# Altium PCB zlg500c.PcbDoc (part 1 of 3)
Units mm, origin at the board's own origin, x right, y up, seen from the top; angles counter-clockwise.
Board outline 135.13 x 130.56 mm, 2 copper layers (Top Layer, Bottom Layer); 79 components, 87 nets, 356 pads, 44 vias.
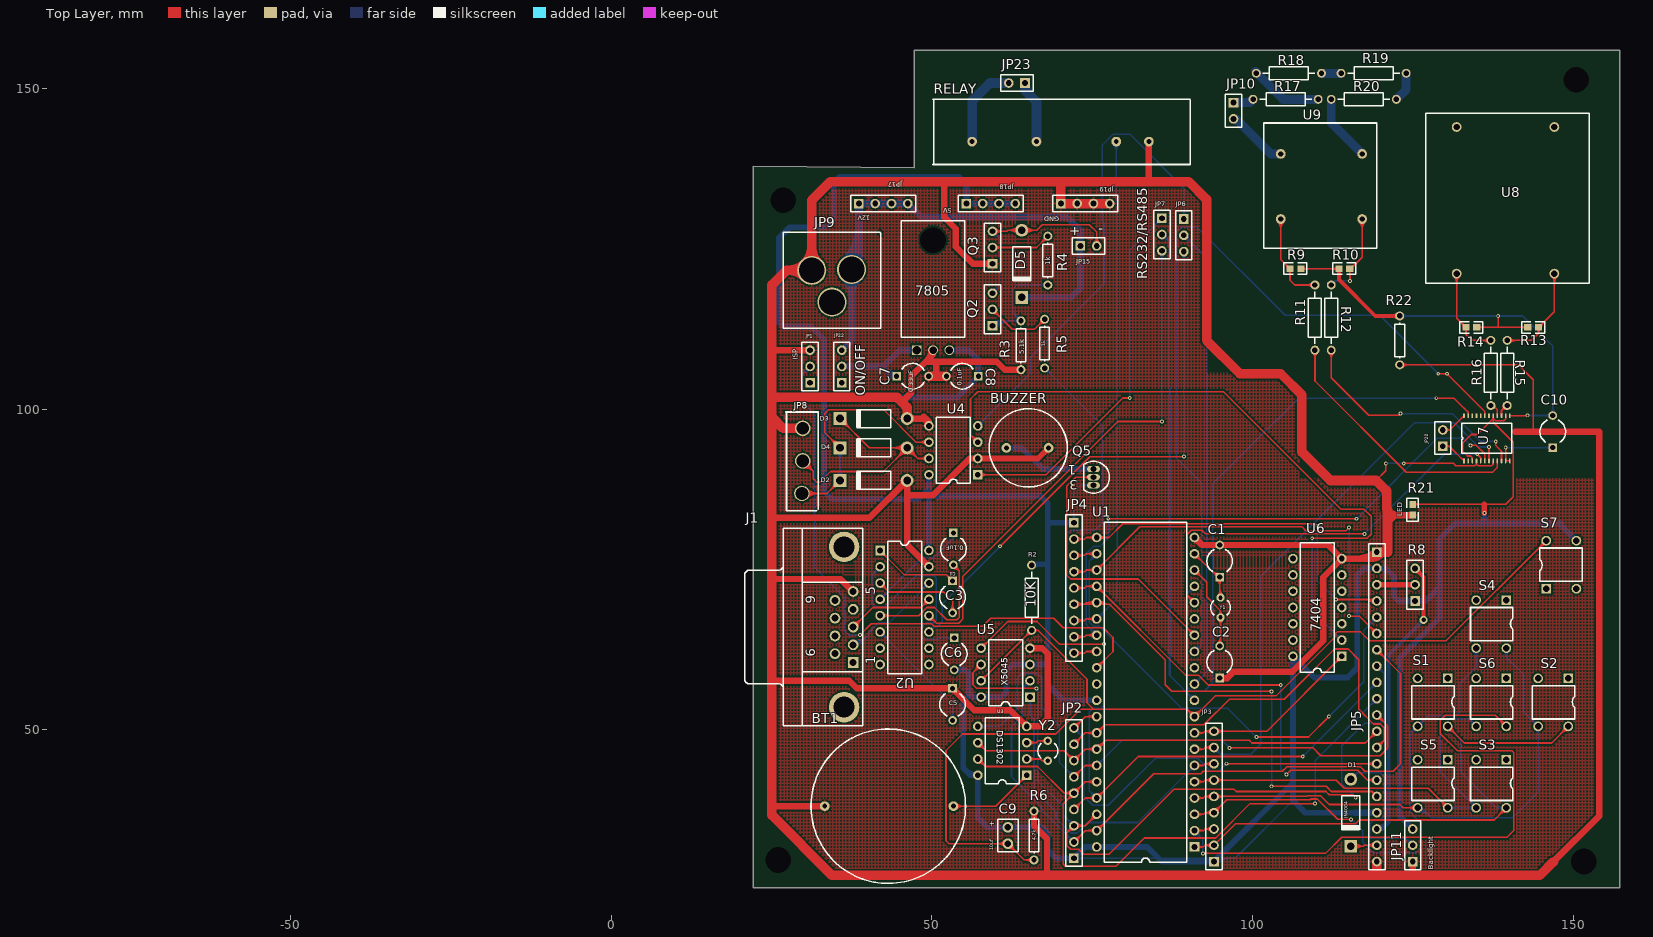
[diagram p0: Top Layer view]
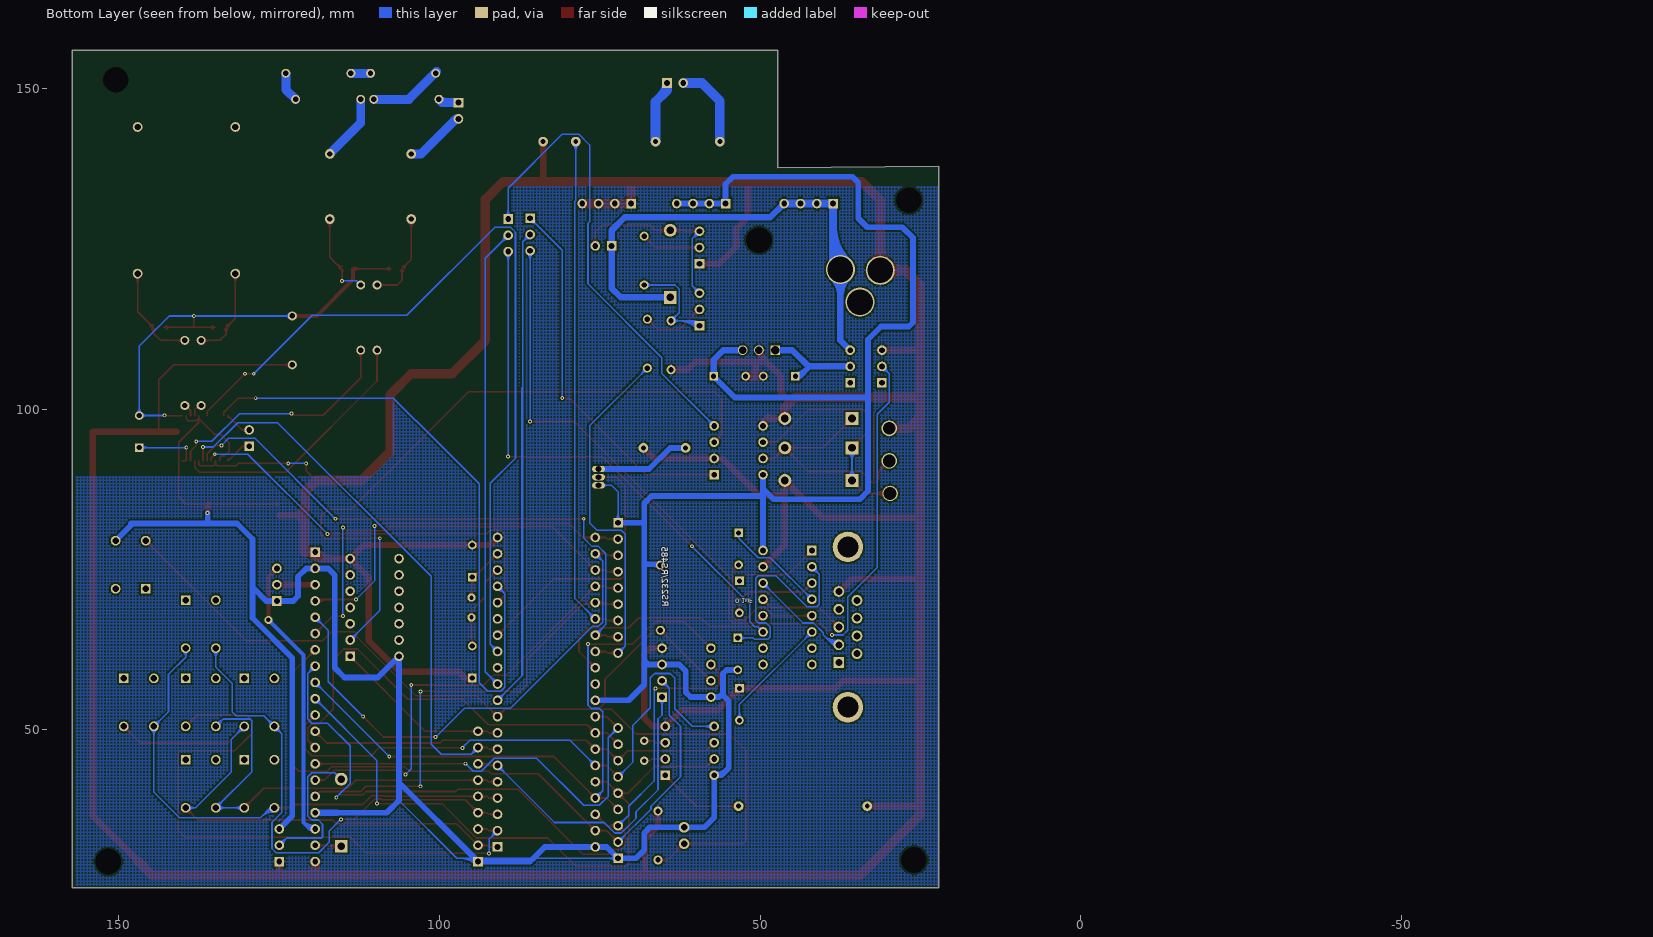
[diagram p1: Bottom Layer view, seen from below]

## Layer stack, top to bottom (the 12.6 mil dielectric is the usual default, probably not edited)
Top Layer: signal copper 0.0356
Dielectric: dielectric 0.32, FR-4, Dk 4.8
Bottom Layer: signal copper 0.0356

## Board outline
22.098,137.922 22.098,25.4 157.226,25.4 157.226,155.956 47.244,155.956 47.244,137.668

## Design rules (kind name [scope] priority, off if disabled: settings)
Clearance [All] p1: gap=0.254
ComponentClearance [All] p1: gap=0.254 collisioncheckmode=0
PolygonConnect [All] p1: connectstyle=Relief reliefconductorwidth=0.254 reliefentries=4 polygonreliefangle="90 Angle"
RoomDefinition zlg500c [InComponentClass('zlg500c')] p1: confinementstyle=ConfineIn formatcopy=TRUE outline 1.397,0 52.197,0 52.197,25.4 1.397,25.4
RoutingLayers [All] p1: top layer=Horizontal bottom layer=Vertical
RoutingVias [All] p1: holewidth=0.3 width=0.6 viastyle="Through Hole" minholewidth=0.3 minwidth=0.6 maxholewidth=0.3 maxwidth=0.6
SolderMaskExpansion [All] p1: expansion=0.102
TestPointUsage [All] p1: valid=0 allowmultiple=FALSE
Testpoint [All] p1: side=15 testpointundercomponent=TRUE minsize=1.016 maxsize=2.54 preferedsize=1.524 minholesize=0 maxholesize=1.016 preferedholesize=0.813 testpointgrid=0.025 style=1023 order=-539222988
Width Width_1 [(InNet('VEE'))] p1: maxlimit=0.6 minlimit=0.254 preferedwidth=0.254 toplayer_minwidth=0.54 toplayer_prefwidth=0.6 bottomlayer_prefwidth=0.6 minimp=50.000000 maximp=50.000000 favimp=50.000000
Width [All] p2: maxlimit=1.5 minlimit=0.2 preferedwidth=0.254 toplayer_prefwidth=1.5 bottomlayer_prefwidth=1 minimp=50.000000 maximp=50.000000 favimp=50.000000
16 further rules are at their usual default settings.

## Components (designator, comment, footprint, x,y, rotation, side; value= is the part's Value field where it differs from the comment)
7805 "7805" T0220 50.165,120.904 r0 top
BT1 "Battery" BATTERY 43.18,38.1 r270 top
BUZZER "BUZZER" BUZZER 62.484,116.84 r180 top
C1 "Cap2" CAPR5-4X5 94.869,76.327 r90 top
C2 "Cap2" CAPR5-4X5 94.869,60.579 r90 top
C3 "Cap2" CAPR5-4X5 53.213,70.739 r270 top
C4 "Cap2" CAPR5-4X5 53.34,78.232 r270 top
C5 "Cap2" CAPR5-4X5 53.213,53.975 r270 top
C6 "Cap2" CAPR5-4X5 53.467,61.849 r270 top
C7 "Cap2" CAPR5-4X5 46.989,105.156 r0 top
C8 "Cap2" CAPR5-4X5 54.737,105.156 r180 top
C9 "Cap" CAPR2.54-5.1X3.2 61.849,33.528 r90 top
C10 "Cap2" CAPR5-4X5 146.812,96.52 r90 top
D1 "Diode 1N4004" DIO10.46-5.3x2.8 115.316,37.084 r270 top
D2 "Diode 11DQ03" DIO10.46-5.3x2.8 40.894,88.9 r180 top
D3 "Diode 11DQ03" DIO10.46-5.3x2.8 40.894,98.552 r180 top
D4 "Diode 11DQ03" DIO10.46-5.3x2.8 40.894,93.98 r180 top
D5 "Diode 1N4004" DIO10.46-5.3x2.8 64.008,122.682 r270 top
J1 "D Connector 9" DSUB1.385-2H9 26.797,66.04 r90 top
JP1 "Header 3" HDR1X3 30.988,104.14 r90 top
JP2 "Header 9" HDR1X9 72.136,29.972 r90 top
JP3 "Header 9" HDR1X9 93.98,29.464 r90 top
JP4 "Header 9" HDR1X9 72.136,82.296 r270 top
JP5 "Header 20" HDR1X20 119.38,77.724 r270 top
JP6 "Header 3" HDR1X3 89.281,129.667 r270 top
JP7 "Header 3" HDR1X3 85.852,129.794 r270 top
JP8 "Header 3" RS485 29.718,91.948 r90 top
JP9 "POWERSLOT" POWERSLOT 34.036,120.396 r180 top
JP10 "Header 2" HDR1X2 97.028,147.828 r270 top
JP11 "Header 3" HDR1X3 124.968,29.464 r90 top
JP15 "Header 2" HDR1X2 73.152,125.476 r0 top
JP17 "Header 4" HDR1X4 38.608,132.08 r0 top
JP18 "Header 4" HDR1X4 55.372,132.08 r0 top
JP19 "Header 4" HDR1X4 70.104,132.08 r0 top
JP20 "Header 2" HDR1X2 129.667,94.234 r90 top
JP22 "Header 3" HDR1X3 35.941,104.14 r90 top
JP23 "AC connector" HDR1X2 64.516,150.876 r180 top
Q2 "2N3904" HDR1X3 59.436,113.03 r90 top
Q3 "2N3904" HDR1X3 59.436,122.682 r90 top
Q5 "2N3904" BCY-W3/E4 75.184,89.408 r180 top
R2 "Res2" AXIAL-0.4 65.532,70.612 r90 top
R3 "Res1" AXIAL-0.3 63.881,109.982 r90 top
R4 "Res1" AXIAL-0.3 68.072,123.19 r270 top
R5 "Res1" AXIAL-0.3 67.564,110.236 r270 top
R6 "Res1" AXIAL-0.3 65.913,33.528 r270 top
R8 "R" HDR1X3 125.349,70.104 r90 top
R9 "Res3" C1608-0603 106.68,121.92 r0 top
R10 "Res3" C1608-0603 114.3,121.92 r0 top
R11 "Res2" AXIAL-0.4 109.728,114.3 r270 top
R12 "Res2" AXIAL-0.4 112.268,114.3 r270 top
R13 "Res3" C1608-0603 143.764,112.776 r180 top
R14 "Res3" C1608-0603 134.112,112.776 r180 top
R15 "Res2" AXIAL-0.4 139.7,105.664 r270 top
R16 "Res2" AXIAL-0.4 137.16,105.664 r270 top
R17 "Res2" AXIAL-0.4 105.156,148.336 r180 top
R18 "Res2" AXIAL-0.4 105.664,152.4 r180 top
R19 "Res2" AXIAL-0.4 118.872,152.4 r180 top
R20 "Res2" AXIAL-0.4 117.348,148.336 r180 top
R21 "Res3" C1608-0603 124.968,84.328 r90 top
R22 "Res1" AXIAL-0.3 122.936,110.744 r270 top
RELAY "Relay_400V5A" RELAY_400V5A 116.332,115.316 r0 top
S1 "" SW_4 128.524,53.848 r270 top
S2 "" SW_4 147.32,53.848 r270 top
S3 "" SW_4 137.668,41.148 r270 top
S4 "" SW_4 137.668,66.04 r270 top
S5 "" SW_4 128.524,41.148 r270 top
S6 "" SW_4 137.668,53.848 r270 top
S7 "" SW_4 147.701,76.2 r90 top
U1 "P89C51RD2HBP" SOT129-1 83.312,55.88 r90 top
U2 "MAX232ACPE" DIP-16 45.72,69.088 r270 top
U3 "DS1302" DIP-8 60.96,46.736 r90 top
U4 "MAX485CPA" DIP-8 53.34,93.599 r90 top
U5 "X5045" dip-8 61.468,58.928 r90 top
U6 "7404" DIP-14 110.109,69.088 r90 top
U7 "CS5460A-BSZ" SOP24 132.969,91.948 r90 top
U8 "TA1419" TA1419 141.732,136.144 r0 top
U9 "TV1013" TV1013 99.06,121.92 r270 top
Y1 "XTAL" BCY-W2/D3.1 94.996,69.088 r0 top
Y2 "XTAL" BCY-W2/D3.1 68.072,46.736 r0 top

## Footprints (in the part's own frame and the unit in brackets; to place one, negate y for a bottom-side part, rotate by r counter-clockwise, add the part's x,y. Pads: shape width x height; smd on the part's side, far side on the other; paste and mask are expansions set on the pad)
AXIAL-0.3 [mm]
  round 1.4 hole 0.85: 1(-3.81,0) 2(3.81,0)
  silkscreen extent -2.77,-0.76 2.77,0.76
AXIAL-0.4 [mm]
  round 1.4 hole 0.85: 1(-5.08,0) 2(5.08,0)
  silkscreen extent -4.06,-1.02 4.06,1.02
BATTERY [mil]
  round 60 hole 30: 1(0,400) 2(0,-390)
  silkscreen extent -474,-474 474,474
BCY-W2/D3.1 [mm]
  round 1.3 hole 0.7: 1(0,1.55) 2(0,-1.55)
  silkscreen extent -1.55,-1.19 1.55,1.17
BCY-W3/E4 [mm]
  oval 2x1 hole 0.9: 1(0,-1.27) 2(0,0) 3(0,1.27)
  silkscreen extent -2.48,-2.48 1.5,2.48
BUZZER [mil]
  round 60 hole 31.5: 0(-225,900) 1(35,900)
  silkscreen extent -340,660 140,1140
C1608-0603 [mm]
  rect 1.1x1 smd: 1(-0.85,0) 2(0.85,0)
  silkscreen extent -1.8,-0.9 1.8,0.9
CAPR2.54-5.1X3.2 [mm]
  round 1.65 hole 1: 1(-1.27,0) 2(1.27,0)
  silkscreen extent -2.55,-1.6 2.55,1.6
CAPR5-4X5 [mm]
  rect 1.35x1.35 hole 0.8: 1(-2.5,0)
  round 1.35 hole 0.8: 2(2.5,0)
  silkscreen extent -1.69,-2 1.82,2
DIO10.46-5.3x2.8 [mm]
  round 2 hole 1.2: 1(-5.23,0)
  rect 2x2 hole 1.2: 2(5.23,0)
  silkscreen extent -2.65,-1.41 2.74,1.4
DIP-8 [mm]
  rect 1.5x1.5 hole 0.9: 1(-3.81,-3.81)
  round 1.5 hole 0.9: 2(-1.27,-3.81) 3(1.27,-3.81) 4(3.81,-3.81) 5(3.81,3.81) 6(1.27,3.81) 7(-1.27,3.81) 8(-3.81,3.81)
  silkscreen extent -5.15,-2.65 5.15,2.65
dip-8 [mm]
  rect 1.5x1.5 hole 0.9: 1(-3.81,-3.81)
  round 1.5 hole 0.9: 2(-1.27,-3.81) 3(1.27,-3.81) 4(3.81,-3.81) 5(3.81,3.81) 6(1.27,3.81) 7(-1.27,3.81) 8(-3.81,3.81)
  silkscreen extent -5.15,-2.65 5.15,2.65
DIP-14 [mm]
  rect 1.5x1.5 hole 0.9: 1(-7.62,-3.81)
  round 1.5 hole 0.9: 2(-5.08,-3.81) 3(-2.54,-3.81) 4(0,-3.81) 5(2.54,-3.81) 6(5.08,-3.81) 7(7.62,-3.81) 8(7.62,3.81) 9(5.08,3.81) 10(2.54,3.81) 11(0,3.81) 12(-2.54,3.81) 13(-5.08,3.81) 14(-7.62,3.81)
  silkscreen extent -10.1,-2.65 10.1,2.65
DIP-16 [mm]
  rect 1.5x1.5 hole 0.9: 1(-8.89,-3.81)
  round 1.5 hole 0.9: 2(-6.35,-3.81) 3(-3.81,-3.81) 4(-1.27,-3.81) 5(1.27,-3.81) 6(3.81,-3.81) 7(6.35,-3.81) 8(8.89,-3.81) 9(8.89,3.81) 10(6.35,3.81) 11(3.81,3.81) 12(1.27,3.81) 13(-1.27,3.81) 14(-3.81,3.81) 15(-6.35,3.81) 16(-8.89,3.81)
  silkscreen extent -10.3,-2.65 10.3,2.65
DSUB1.385-2H9 [mm] "Connector; D Subminiature; 9 Position; Right Angle; Pitch 1.385 mm"
  rect 1.69x1.69 hole 1.09: 1(-5.54,-10.92)
  round 1.69 hole 1.09: 2(-2.77,-10.92) 3(0,-10.92) 4(2.77,-10.92) 5(5.54,-10.92) 6(-4.155,-8.08) 7(-1.385,-8.08) 8(1.385,-8.08) 9(4.155,-8.08)
  round 4.76 hole 3.26: 10(-12.495,-9.5) 11(12.495,-9.5)
  silkscreen extent -15.4,-12.4 15.4,6
HDR1X2 [mm] "Connector; Header; 2 Position"
  rect 1.5x1.5 hole 0.9: 1(0,0)
  round 1.5 hole 0.9: 2(2.54,0)
  silkscreen extent -1.27,-1.27 3.81,1.27
HDR1X3 [mm] "Connector; Header; 3 Position"
  rect 1.5x1.5 hole 0.9: 1(0,0)
  round 1.5 hole 0.9: 2(2.54,0) 3(5.08,0)
  silkscreen extent -1.27,-1.27 6.35,1.27
HDR1X4 [mm] "Connector; Header; 4 Position"
  rect 1.5x1.5 hole 0.9: 1(0,0)
  round 1.5 hole 0.9: 2(2.54,0) 3(5.08,0) 4(7.62,0)
  silkscreen extent -1.27,-1.27 8.89,1.27
HDR1X9 [mm] "Connector; Header; 9 Position"
  rect 1.5x1.5 hole 0.9: 1(0,0)
  round 1.5 hole 0.9: 2(2.54,0) 3(5.08,0) 4(7.62,0) 5(10.16,0) 6(12.7,0) 7(15.24,0) 8(17.78,0) 9(20.32,0)
  silkscreen extent -1.27,-1.27 21.59,1.27
HDR1X20 [mm] "Connector; Header; 20 Position"
  rect 1.5x1.5 hole 0.9: 1(0,0)
  round 1.5 hole 0.9: 2(2.54,0) 3(5.08,0) 4(7.62,0) 5(10.16,0) 6(12.7,0) 7(15.24,0) 8(17.78,0) 9(20.32,0) 10(22.86,0) 11(25.4,0) 12(27.94,0) 13(30.48,0) 14(33.02,0) 15(35.56,0) 16(38.1,0) 17(40.64,0) 18(43.18,0) 19(45.72,0) 20(48.26,0)
  silkscreen extent -1.27,-1.27 49.53,1.27
POWERSLOT [mil]
  round 178.11 hole 157.48: 1(-15,145) 2(110,-50) 3(-135,-55)
  Top Layer lines w10: -310,-285 -310,-275 -315,-270
  silkscreen extent -315,-285 285,305
RELAY_400V5A [mil]
  round 60 hole 30: 0(-1280,1040) 1(-1480,1040) 2(-1970,1040) 3(-2365,1040)
  silkscreen extent -2605,900 -1025,1300
RS485 [mm]
  round 2.424 hole 2: 1(-5.08,0) 2(0,-0.127) 3(5.08,-0.127)
  Top Layer lines w0.254: 7.62,2.54 7.493,2.413 ; -7.747,-2.286 -7.493,-2.54 ; -2.794,-2.54 7.62,-2.54
  silkscreen extent -7.75,-2.54 7.62,2.54
SOP24 [mm]
  rect 0.75x0.26 smd: 1(0,0)
  oval 0.75x0.26 smd: 2(0,-0.65) 3(0,-1.3) 4(0,-1.95) 5(0,-2.6) 6(0,-3.25) 7(0,-3.9) 8(0,-4.55) 9(0,-5.2) 10(0,-5.85) 11(0,-6.5) 12(0,-7.15) 13(7.05,-7.15) 14(7.05,-6.5) 15(7.05,-5.85) 16(7.05,-5.2) 17(7.05,-4.55) 18(7.05,-3.9) 19(7.05,-3.25) 20(7.05,-2.6) 21(7.05,-1.95) 22(7.05,-1.3) 23(7.05,-0.65) 24(7.05,0)
  silkscreen extent 1.21,-7.48 5.84,0.33
SOT129-1 [mm] "DIP; 40 Leads; Row Spacing 15.24 mm; Pitch 2.54 mm"
  rect 1.5x1.5 hole 0.9: 1(-24.13,-7.62)
  round 1.5 hole 0.9: 2(-21.59,-7.62) 3(-19.05,-7.62) 4(-16.51,-7.62) 5(-13.97,-7.62) 6(-11.43,-7.62) 7(-8.89,-7.62) 8(-6.35,-7.62) 9(-3.81,-7.62) 10(-1.27,-7.62) 11(1.27,-7.62) 12(3.81,-7.62) 13(6.35,-7.62) 14(8.89,-7.62) 15(11.43,-7.62) 16(13.97,-7.62) 17(16.51,-7.62) 18(19.05,-7.62) 19(21.59,-7.62) 20(24.13,-7.62) 21(24.13,7.62) 22(21.59,7.62) 23(19.05,7.62) 24(16.51,7.62) 25(13.97,7.62) 26(11.43,7.62) 27(8.89,7.62) 28(6.35,7.62) 29(3.81,7.62) 30(1.27,7.62) 31(-1.27,7.62) 32(-3.81,7.62) 33(-6.35,7.62) 34(-8.89,7.62) 35(-11.43,7.62) 36(-13.97,7.62) 37(-16.51,7.62) 38(-19.05,7.62) 39(-21.59,7.62) 40(-24.13,7.62)
  silkscreen extent -26.5,-6.45 26.5,6.45
SW_4 [mil]
  rect 60x60 hole 39.37: 1(-165,75)
  round 60 hole 39.37: 2(-165,-110) 3(130,-110) 4(130,75)
  silkscreen extent -120,-145 85,115
T0220 [mil] "T0220"
  rect 60x60 hole 53.62: 0(-100,-460)
  round 60 hole 45.75: 1(0,-460) 2(100,-460)
  round 0 hole 157.48: 4(0,215)
  silkscreen extent -195,-380 195,335
TA1419 [mil]
  round 60 hole 39.37: 1(-390,-590) 2(210,-590) 3(210,310) 4(-390,310)
  silkscreen extent -580,-650 425,395
TV1013 [mil]
  round 60 hole 31.5: 1(-705,710) 2(-705,210) 3(-305,210) 4(-305,710)
  silkscreen extent -895,105 -125,800

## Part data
BT1: "Multicell Battery"
C1 C2 C3 C4 C5 C6 C9 C10: "Capacitor"
C7 C8: library part Cap, "Capacitor"
D1 D5: "1 Amp General Purpose Rectifier"
D2 D3 D4: library part "Diode 18TQ045", "Schottky Rectifier"
J1: "Receptacle Assembly, 9 Position, Right Angle"
JP1 JP6 JP7 JP8 JP11 JP22: "Header, 3-Pin"
JP2 JP3 JP4: "Header, 9-Pin"
JP5: "Header, 20-Pin"
JP9: library part "Header 3", "Header, 3-Pin"
JP10 JP15 JP20: "Header, 2-Pin"
JP17 JP18 JP19: "Header, 4-Pin"
JP23: library part "Header 2", "Header, 2-Pin"
Q2 Q3 Q5: "NPN General Purpose Amplifier"
R2 R3 R4 R5 R6 R11 R12 R15 R16 R17 R18 R19 R20 R21 R22: "Resistor"
R8: library part RPot, "Potentiometer"
R9 R10 R13 R14: library part Res2, "Resistor"
S1 S2 S3 S4 S5 S6: library part SW-PB, "Switch"
S7: library part SW-DPST, "Double-Pole, Single-Throw Switch"
U1: "80C51 8-Bit Flash Microcontroller Family, 64 kB ISP/IAP Flash with 1 kB RAM."
U2: "+5V Powered, Multi-Channel RS-232 Driver/Receiver"
U3: "Trickle Charge Timekeeping Chip"
U4: "Low-Power, Slew-Rate-Limited RS-485/RS-422 Transceiver"
U6: library part 74AC04PC, "Hex Inverter"
Y1 Y2: "Crystal Oscillator"

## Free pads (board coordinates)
  round 0 hole 4: 0(-82.042,29.972) 0(-81.661,120.523) 0(-79.756,118.618) 0(26.035,29.718) 0(26.797,132.588) 0(150.495,151.384) 0(151.638,29.464)

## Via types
v1: diameter 0.6, hole 0.3, Top Layer to Bottom Layer, 43 vias
v2: diameter 1.27, hole 0.711, Top Layer to Bottom Layer, 1 vias

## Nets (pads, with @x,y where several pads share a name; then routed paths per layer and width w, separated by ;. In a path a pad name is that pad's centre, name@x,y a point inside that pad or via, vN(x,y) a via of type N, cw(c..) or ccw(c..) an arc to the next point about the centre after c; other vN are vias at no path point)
A: D1.2 JP5.19 | length 12.9
  Top Layer w0.254: D1.2@115.316,31.854 117.272,31.854 ; D1.2@115.777,31.441 cw(c116.703,30.61) 116.703,31.854 cw(c116.703,33.098) D1.2@115.777,32.267 ; D1.2@115.966,31.271 cw(c117.272,30.1) 117.272,31.854 ; D1.2@115.966,32.437 ccw(c117.272,33.608) 117.272,31.854 ; JP5.19@118.939,31.563 ccw(c117.876,30.5) 117.876,32.004 ccw(c117.876,33.508) JP5.19@118.939,32.445 ; JP5.19@119.119,31.743 ccw(c118.489,31.113) 118.489,32.004 ccw(c118.489,32.895) JP5.19@119.119,32.265 ; JP5.19@119.38,32.004 117.422,32.004 117.272,31.854
AD0: JP2.2 JP5.7 U1.39 U5.2 | length 143.8
  Top Layer w0.254: JP2.2@72.136,32.512 73.914,34.29 U1.39@75.692,34.29 84.582,43.18 91.948,43.18 92.304,43.536 104.623,43.536 105.308,44.221 116.847,44.221 117.507,43.561 121.92,43.561 123.063,44.704 123.063,58.801 JP5.7@119.38,62.484 ; JP5.7@119.38,61.861 cw(c119.38,60.357) 120.444,61.42 cw(c121.507,62.484) JP5.7@120.003,62.484 ; JP5.7@119.38,62.115 cw(c119.38,61.224) 120.01,61.854 cw(c120.64,62.484) JP5.7@119.749,62.484 ; 72.766,33.142 cw(c72.136,33.772) 72.136,32.881 ccw(c72.136,33.772) 72.766,33.142 ; 72.766,33.142 ccw(c73.396,32.512) 72.505,32.512 cw(c73.396,32.512) 72.766,33.142 ; 73.2,33.576 cw(c72.136,34.639) 72.136,33.135 ccw(c72.136,34.639) 73.2,33.576 ; 73.2,33.576 ccw(c74.263,32.512) 72.759,32.512 cw(c74.263,32.512) 73.2,33.576 ; 74.188,34.29 cw(c74.188,32.786) 75.251,33.849 ccw(c74.188,32.786) 74.188,34.29 ; 74.188,34.29 ccw(c74.188,35.794) 75.251,34.731 cw(c74.188,35.794) 74.188,34.29 ; 74.801,34.29 cw(c74.801,33.399) 75.431,34.029 ccw(c74.801,33.399) 74.801,34.29 ; 74.801,34.29 ccw(c74.801,35.181) 75.431,34.551 cw(c74.801,35.181) 74.801,34.29 ; 76.322,34.92 cw(c75.692,35.55) 75.692,34.659 ccw(c75.692,35.55) 76.322,34.92 ; 76.322,34.92 ccw(c76.952,34.29) 76.061,34.29 cw(c76.952,34.29) 76.322,34.92 ; 76.756,35.354 cw(c75.692,36.417) 75.692,34.913 ccw(c75.692,36.417) 76.756,35.354 ; 76.756,35.354 ccw(c77.819,34.29) 76.315,34.29 cw(c77.819,34.29) 76.756,35.354
  Bottom Layer w0.254: U5.2@65.278,57.658 64.135,56.515 64.135,52.273 62.408,50.546 62.408,42.697 67.005,38.1 67.005,37.643 JP2.2@72.136,32.512 ; JP2.2@71.513,32.512 ccw(c70.009,32.512) 71.072,33.576 ccw(c72.136,34.639) JP2.2@72.136,33.135 ; JP2.2@71.767,32.512 ccw(c70.876,32.512) 71.506,33.142 ccw(c72.136,33.772) JP2.2@72.136,32.881 ; 64.214,56.594 cw(c65.278,55.531) 65.278,57.035 ccw(c65.278,55.531) 64.214,56.594 ; 64.214,56.594 ccw(c63.151,57.658) 64.655,57.658 cw(c63.151,57.658) 64.214,56.594 ; 64.648,57.028 cw(c65.278,56.398) 65.278,57.289 ccw(c65.278,56.398) 64.648,57.028 ; 64.648,57.028 ccw(c64.018,57.658) 64.909,57.658 cw(c64.018,57.658) 64.648,57.028
AD1: JP2.3 JP5.8 U1.38 U5.6 | length 163.3
  Top Layer w0.254: U5.6@57.035,60.198 cw(c55.531,60.198) 56.594,59.134 cw(c57.658,58.071) U5.6@57.658,59.575 ; U5.6@57.289,60.198 cw(c56.398,60.198) 57.028,59.568 cw(c57.658,58.938) U5.6@57.658,59.829 ; U5.6@57.658,60.198 56.388,58.928 56.388,57.048 56.972,56.464 v1(66.319,56.464) ; U1.38@75.692,36.83 73.914,35.052 JP2.3@72.136,35.052 70.993,33.909 70.993,32.004 71.628,31.369 72.898,31.369 73.66,30.607 77.622,30.607 87.782,40.767 97.053,40.767 97.434,40.386 111.455,40.386 111.963,39.878 115.672,39.878 v1(116.078,39.472) ; 71.072,33.988 cw(c72.136,32.925) 72.136,34.429 ccw(c72.136,32.925) 71.072,33.988 ; 71.072,33.988 ccw(c70.009,35.052) 71.513,35.052 cw(c70.009,35.052) 71.072,33.988 ; 71.506,34.422 cw(c72.136,33.792) 72.136,34.683 ccw(c72.136,33.792) 71.506,34.422 ; 71.506,34.422 ccw(c70.876,35.052) 71.767,35.052 cw(c70.876,35.052) 71.506,34.422 ; 73.027,35.052 cw(c73.027,35.943) 72.397,35.313 ccw(c73.027,35.943) 73.027,35.052 ; 73.027,35.052 ccw(c73.027,34.161) 72.397,34.791 cw(c73.027,34.161) 73.027,35.052 ; 73.64,35.052 cw(c73.64,36.556) 72.577,35.493 ccw(c73.64,36.556) 73.64,35.052 ; 73.64,35.052 ccw(c73.64,33.548) 72.577,34.611 cw(c73.64,33.548) 73.64,35.052 ; 74.628,35.766 cw(c75.692,34.703) 75.692,36.207 ccw(c75.692,34.703) 74.628,35.766 ; 74.628,35.766 ccw(c73.565,36.83) 75.069,36.83 cw(c73.565,36.83) 74.628,35.766 ; 75.062,36.2 cw(c75.692,35.57) 75.692,36.461 ccw(c75.692,35.57) 75.062,36.2 ; 75.062,36.2 ccw(c74.432,36.83) 75.323,36.83 cw(c74.432,36.83) 75.062,36.2
  Bottom Layer w0.254: v1(66.319,56.464) 66.523,56.261 66.523,42.037 70.485,38.075 70.485,36.703 JP2.3@72.136,35.052 ; v1(116.078,39.472) 113.919,41.631 113.919,47.523 117.45,51.054 119.888,51.054 120.523,51.689 120.523,58.801 JP5.8@119.38,59.944 ; 71.072,36.116 cw(c70.009,35.052) 71.513,35.052 ccw(c70.009,35.052) 71.072,36.116 ; 71.072,36.116 ccw(c72.136,37.179) 72.136,35.675 cw(c72.136,37.179) 71.072,36.116 ; 71.506,35.682 cw(c70.876,35.052) 71.767,35.052 ccw(c70.876,35.052) 71.506,35.682 ; 71.506,35.682 ccw(c72.136,36.312) 72.136,35.421 cw(c72.136,36.312) 71.506,35.682 ; 120.01,59.314 cw(c120.64,59.944) 119.749,59.944 ccw(c120.64,59.944) 120.01,59.314 ; 120.01,59.314 ccw(c119.38,58.684) 119.38,59.575 cw(c119.38,58.684) 120.01,59.314 ; 120.444,58.88 cw(c121.507,59.944) 120.003,59.944 ccw(c121.507,59.944) 120.444,58.88 ; 120.444,58.88 ccw(c119.38,57.817) 119.38,59.321 cw(c119.38,57.817) 120.444,58.88
AD2: JP2.4 JP5.9 U1.37 U5.5 | length 145.4
  Top Layer w0.254: U5.5@57.658,62.738 61.824,66.904 66.37,66.904 69.901,63.373 v1(76.835,63.373) ; U5.5@57.658,63.107 ccw(c57.658,63.998) 58.288,63.368 ccw(c58.918,62.738) U5.5@58.027,62.738 ; U5.5@57.658,63.361 ccw(c57.658,64.865) 58.722,63.802 ccw(c59.785,62.738) U5.5@58.281,62.738 ; JP2.4@72.136,37.592 73.914,39.37 U1.37@75.692,39.37 82.169,45.847 v1(107.823,45.847) ; 72.766,38.222 cw(c72.136,38.852) 72.136,37.961 ccw(c72.136,38.852) 72.766,38.222 ; 72.766,38.222 ccw(c73.396,37.592) 72.505,37.592 cw(c73.396,37.592) 72.766,38.222 ; 73.2,38.656 cw(c72.136,39.719) 72.136,38.215 ccw(c72.136,39.719) 73.2,38.656 ; 73.2,38.656 ccw(c74.263,37.592) 72.759,37.592 cw(c74.263,37.592) 73.2,38.656 ; 74.188,39.37 cw(c74.188,37.866) 75.251,38.929 ccw(c74.188,37.866) 74.188,39.37 ; 74.188,39.37 ccw(c74.188,40.874) 75.251,39.811 cw(c74.188,40.874) 74.188,39.37 ; 74.801,39.37 cw(c74.801,38.479) 75.431,39.109 ccw(c74.801,38.479) 74.801,39.37 ; 74.801,39.37 ccw(c74.801,40.261) 75.431,39.631 cw(c74.801,40.261) 74.801,39.37 ; 76.322,40 cw(c75.692,40.63) 75.692,39.739 ccw(c75.692,40.63) 76.322,40 ; 76.322,40 ccw(c76.952,39.37) 76.061,39.37 cw(c76.952,39.37) 76.322,40 ; 76.756,40.434 cw(c75.692,41.497) 75.692,39.993 ccw(c75.692,41.497) 76.756,40.434 ; 76.756,40.434 ccw(c77.819,39.37) 76.315,39.37 cw(c77.819,39.37) 76.756,40.434
  Bottom Layer w0.254: U1.37@75.692,39.37 74.549,40.513 74.549,52.832 75.057,53.34 76.327,53.34 76.835,53.848 v1(76.835,63.373) ; v1(107.823,45.847) JP5.9@119.38,57.404 ; 74.628,40.434 cw(c73.565,39.37) 75.069,39.37 ccw(c73.565,39.37) 74.628,40.434 ; 74.628,40.434 ccw(c75.692,41.497) 75.692,39.993 cw(c75.692,41.497) 74.628,40.434 ; 75.062,40 cw(c74.432,39.37) 75.323,39.37 ccw(c74.432,39.37) 75.062,40 ; 75.062,40 ccw(c75.692,40.63) 75.692,39.739 cw(c75.692,40.63) 75.062,40 ; 118.316,56.34 cw(c119.38,55.277) 119.38,56.781 ccw(c119.38,55.277) 118.316,56.34 ; 118.316,56.34 ccw(c117.253,57.404) 118.757,57.404 cw(c117.253,57.404) 118.316,56.34 ; 118.75,56.774 cw(c119.38,56.144) 119.38,57.035 ccw(c119.38,56.144) 118.75,56.774 ; 118.75,56.774 ccw(c118.12,57.404) 119.011,57.404 cw(c118.12,57.404) 118.75,56.774
AD3: JP2.5 JP5.10 U1.36 U3.7 | length 134.6
  Top Layer w0.254: U3.7@57.15,45.466 58.318,44.298 66.472,44.298 70.637,40.132 ; JP2.5@71.513,40.132 cw(c70.009,40.132) 71.072,39.068 cw(c72.136,38.005) JP2.5@72.136,39.509 ; JP2.5@71.694,39.693 ccw(c70.637,38.641) 70.637,40.132 ; JP2.5@71.694,40.571 cw(c70.637,41.623) 70.637,40.132 ; JP2.5@71.767,40.132 cw(c70.876,40.132) 71.506,39.502 cw(c72.136,38.872) JP2.5@72.136,39.763 ; JP2.5@71.874,39.872 ccw(c71.248,39.249) 71.248,40.132 ccw(c71.248,41.015) JP2.5@71.874,40.392 ; U1.36@75.692,41.91 73.914,41.91 JP2.5@72.136,40.132 ; v1(109.753,38.506) 99.593,38.506 94.234,33.147 83.083,33.147 78.689,28.753 70.79,28.753 70.485,29.058 70.485,38.481 JP2.5@72.136,40.132 ; 57.78,44.836 cw(c58.41,45.466) 57.519,45.466 ccw(c58.41,45.466) 57.78,44.836 ; 57.78,44.836 ccw(c57.15,44.206) 57.15,45.097 cw(c57.15,44.206) 57.78,44.836 ; 58.214,44.402 cw(c59.277,45.466) 57.773,45.466 ccw(c59.277,45.466) 58.214,44.402 ; 58.214,44.402 ccw(c57.15,43.339) 57.15,44.843 cw(c57.15,43.339) 58.214,44.402 ; 70.637,40.132 JP2.5@72.136,40.132 ; 72.766,40.762 cw(c72.136,41.392) 72.136,40.501 ccw(c72.136,41.392) 72.766,40.762 ; 72.766,40.762 ccw(c73.396,40.132) 72.505,40.132 cw(c73.396,40.132) 72.766,40.762 ; 73.2,41.196 cw(c72.136,42.259) 72.136,40.755 ccw(c72.136,42.259) 73.2,41.196 ; 73.2,41.196 ccw(c74.263,40.132) 72.759,40.132 cw(c74.263,40.132) 73.2,41.196 ; 74.188,41.91 cw(c74.188,40.406) 75.251,41.469 ccw(c74.188,40.406) 74.188,41.91 ; 74.188,41.91 ccw(c74.188,43.414) 75.251,42.351 cw(c74.188,43.414) 74.188,41.91 ; 74.801,41.91 cw(c74.801,41.019) 75.431,41.649 ccw(c74.801,41.019) 74.801,41.91 ; 74.801,41.91 ccw(c74.801,42.801) 75.431,42.171 cw(c74.801,42.801) 74.801,41.91
  Bottom Layer w0.254: v1(109.753,38.506) 109.753,45.237 JP5.10@119.38,54.864 ; 118.316,53.8 cw(c119.38,52.737) 119.38,54.241 ccw(c119.38,52.737) 118.316,53.8 ; 118.316,53.8 ccw(c117.253,54.864) 118.757,54.864 cw(c117.253,54.864) 118.316,53.8 ; 118.75,54.234 cw(c119.38,53.604) 119.38,54.495 ccw(c119.38,53.604) 118.75,54.234 ; 118.75,54.234 ccw(c118.12,54.864) 119.011,54.864 cw(c118.12,54.864) 118.75,54.234
AD4: JP2.6 JP5.11 U1.35 U3.5 | length 134
  Top Layer w0.254: JP2.6@72.136,42.672 73.914,44.45 U1.35@75.692,44.45 ; v1(96.418,47.193) 109.423,47.193 110.642,45.974 119.888,45.974 121.031,47.117 121.031,50.673 JP5.11@119.38,52.324 ; 72.766,43.302 cw(c72.136,43.932) 72.136,43.041 ccw(c72.136,43.932) 72.766,43.302 ; 72.766,43.302 ccw(c73.396,42.672) 72.505,42.672 cw(c73.396,42.672) 72.766,43.302 ; 73.2,43.736 cw(c72.136,44.799) 72.136,43.295 ccw(c72.136,44.799) 73.2,43.736 ; 73.2,43.736 ccw(c74.263,42.672) 72.759,42.672 cw(c74.263,42.672) 73.2,43.736 ; 74.188,44.45 cw(c74.188,42.946) 75.251,44.009 ccw(c74.188,42.946) 74.188,44.45 ; 74.188,44.45 ccw(c74.188,45.954) 75.251,44.891 cw(c74.188,45.954) 74.188,44.45 ; 74.801,44.45 cw(c74.801,43.559) 75.431,44.189 ccw(c74.801,43.559) 74.801,44.45 ; 74.801,44.45 ccw(c74.801,45.341) 75.431,44.711 cw(c74.801,45.341) 74.801,44.45 ; 120.01,51.694 cw(c120.64,52.324) 119.749,52.324 ccw(c120.64,52.324) 120.01,51.694 ; 120.01,51.694 ccw(c119.38,51.064) 119.38,51.955 cw(c119.38,51.064) 120.01,51.694 ; 120.444,51.26 cw(c121.507,52.324) 120.003,52.324 ccw(c121.507,52.324) 120.444,51.26 ; 120.444,51.26 ccw(c119.38,50.197) 119.38,51.701 cw(c119.38,50.197) 120.444,51.26
  Bottom Layer w0.254: U3.5@57.15,50.546 60.554,50.546 63.297,53.289 63.297,58.09 64.008,58.801 66.421,58.801 67.107,58.115 67.107,53.442 69.825,50.724 69.825,44.983 JP2.6@72.136,42.672 ; U3.5@57.411,50.285 cw(c58.041,49.655) 58.041,50.546 cw(c58.041,51.437) U3.5@57.411,50.807 ; U3.5@57.591,50.105 cw(c58.654,49.042) 58.654,50.546 cw(c58.654,52.05) U3.5@57.591,50.987 ; U1.35@75.692,44.45 79.629,48.387 95.225,48.387 v1(96.418,47.193) ; 71.072,43.736 cw(c70.009,42.672) 71.513,42.672 ccw(c70.009,42.672) 71.072,43.736 ; 71.072,43.736 ccw(c72.136,44.799) 72.136,43.295 cw(c72.136,44.799) 71.072,43.736 ; 71.506,43.302 cw(c70.876,42.672) 71.767,42.672 ccw(c70.876,42.672) 71.506,43.302 ; 71.506,43.302 ccw(c72.136,43.932) 72.136,43.041 cw(c72.136,43.932) 71.506,43.302 ; 76.322,45.08 cw(c75.692,45.71) 75.692,44.819 ccw(c75.692,45.71) 76.322,45.08 ; 76.322,45.08 ccw(c76.952,44.45) 76.061,44.45 cw(c76.952,44.45) 76.322,45.08 ; 76.756,45.514 cw(c75.692,46.577) 75.692,45.073 ccw(c75.692,46.577) 76.756,45.514 ; 76.756,45.514 ccw(c77.819,44.45) 76.315,44.45 cw(c77.819,44.45) 76.756,45.514
AD5: JP2.7 JP5.12 U1.34 U3.6 | length 110.8
  Top Layer w0.254: U3.6@57.15,48.006 58.42,46.736 70.612,46.736 JP2.7@72.136,45.212 73.914,46.99 U1.34@75.692,46.99 77.089,48.387 99.466,48.387 99.898,47.955 117.551,47.955 JP5.12@119.38,49.784 ; 57.78,47.376 cw(c58.41,48.006) 57.519,48.006 ccw(c58.41,48.006) 57.78,47.376 ; 57.78,47.376 ccw(c57.15,46.746) 57.15,47.637 cw(c57.15,46.746) 57.78,47.376 ; 58.214,46.942 cw(c59.277,48.006) 57.773,48.006 ccw(c59.277,48.006) 58.214,46.942 ; 58.214,46.942 ccw(c57.15,45.879) 57.15,47.383 cw(c57.15,45.879) 58.214,46.942 ; 71.072,46.276 cw(c70.009,45.212) 71.513,45.212 ccw(c70.009,45.212) 71.072,46.276 ; 71.072,46.276 ccw(c72.136,47.339) JP2.7@72.136,45.835 ; 71.072,46.276 ccw(c72.136,47.339) JP2.7@72.136,45.835 ; 71.506,45.842 cw(c70.876,45.212) 71.767,45.212 ccw(c70.876,45.212) 71.506,45.842 ; 71.506,45.842 ccw(c72.136,46.472) JP2.7@72.136,45.581 ; 71.506,45.842 ccw(c72.136,46.472) JP2.7@72.136,45.581 ; JP2.7@72.136,45.581 ccw(c72.136,46.472) 72.766,45.842 ; JP2.7@72.136,45.581 ccw(c72.136,46.472) 72.766,45.842 ; JP2.7@72.136,45.835 ccw(c72.136,47.339) 73.2,46.276 ; JP2.7@72.136,45.835 ccw(c72.136,47.339) 73.2,46.276 ; 72.766,45.842 ccw(c73.396,45.212) 72.505,45.212 cw(c73.396,45.212) 72.766,45.842 ; 73.2,46.276 ccw(c74.263,45.212) 72.759,45.212 cw(c74.263,45.212) 73.2,46.276 ; 74.188,46.99 cw(c74.188,45.486) 75.251,46.549 ccw(c74.188,45.486) 74.188,46.99 ; 74.188,46.99 ccw(c74.188,48.494) 75.251,47.431 cw(c74.188,48.494) 74.188,46.99 ; 74.801,46.99 cw(c74.801,46.099) 75.431,46.729 ccw(c74.801,46.099) 74.801,46.99 ; 74.801,46.99 ccw(c74.801,47.881) 75.431,47.251 cw(c74.801,47.881) 74.801,46.99 ; 76.322,47.62 cw(c75.692,48.25) 75.692,47.359 ccw(c75.692,48.25) 76.322,47.62 ; 76.322,47.62 ccw(c76.952,46.99) 76.061,46.99 cw(c76.952,46.99) 76.322,47.62 ; 76.756,48.054 cw(c75.692,49.117) 75.692,47.613 ccw(c75.692,49.117) 76.756,48.054 ; 76.756,48.054 ccw(c77.819,46.99) 76.315,46.99 cw(c77.819,46.99) 76.756,48.054 ; 118.316,48.72 cw(c119.38,47.657) 119.38,49.161 ccw(c119.38,47.657) 118.316,48.72 ; 118.316,48.72 ccw(c117.253,49.784) 118.757,49.784 cw(c117.253,49.784) 118.316,48.72 ; 118.75,49.154 cw(c119.38,48.524) 119.38,49.415 ccw(c119.38,48.524) 118.75,49.154 ; 118.75,49.154 ccw(c118.12,49.784) 119.011,49.784 cw(c118.12,49.784) 118.75,49.154
AD6: JP2.8 JP5.13 U1.33 | length 97.8
  Top Layer w0.254: JP2.8@72.136,47.752 73.914,49.53 U1.33@75.692,49.53 76.962,50.8 92.405,50.8 96.393,54.788 104.953,54.788 112.776,62.611 114.91,62.611 116.561,60.96 116.561,53.213 118.847,50.927 119.888,50.927 120.523,50.292 120.523,48.387 JP5.13@119.38,47.244 ; 72.766,48.382 cw(c72.136,49.012) 72.136,48.121 ccw(c72.136,49.012) 72.766,48.382 ; 72.766,48.382 ccw(c73.396,47.752) 72.505,47.752 cw(c73.396,47.752) 72.766,48.382 ; 73.2,48.816 cw(c72.136,49.879) 72.136,48.375 ccw(c72.136,49.879) 73.2,48.816 ; 73.2,48.816 ccw(c74.263,47.752) 72.759,47.752 cw(c74.263,47.752) 73.2,48.816 ; 74.188,49.53 cw(c74.188,48.026) 75.251,49.089 ccw(c74.188,48.026) 74.188,49.53 ; 74.188,49.53 ccw(c74.188,51.034) 75.251,49.971 cw(c74.188,51.034) 74.188,49.53 ; 74.801,49.53 cw(c74.801,48.639) 75.431,49.269 ccw(c74.801,48.639) 74.801,49.53 ; 74.801,49.53 ccw(c74.801,50.421) 75.431,49.791 cw(c74.801,50.421) 74.801,49.53 ; 76.322,50.16 cw(c75.692,50.79) 75.692,49.899 ccw(c75.692,50.79) 76.322,50.16 ; 76.322,50.16 ccw(c76.952,49.53) 76.061,49.53 cw(c76.952,49.53) 76.322,50.16 ; 76.756,50.594 cw(c75.692,51.657) 75.692,50.153 ccw(c75.692,51.657) 76.756,50.594 ; 76.756,50.594 ccw(c77.819,49.53) 76.315,49.53 cw(c77.819,49.53) 76.756,50.594 ; 120.01,47.874 cw(c119.38,48.504) 119.38,47.613 ccw(c119.38,48.504) 120.01,47.874 ; 120.01,47.874 ccw(c120.64,47.244) 119.749,47.244 cw(c120.64,47.244) 120.01,47.874 ; 120.444,48.308 cw(c119.38,49.371) 119.38,47.867 ccw(c119.38,49.371) 120.444,48.308 ; 120.444,48.308 ccw(c121.507,47.244) 120.003,47.244 cw(c121.507,47.244) 120.444,48.308
AD7: JP2.9 JP5.14 U1.32 | length 96.4
  Top Layer w0.254: JP2.9@72.136,50.292 73.914,52.07 U1.32@75.692,52.07 ; v1(95.91,44.729) 117.373,44.729 117.399,44.704 JP5.14@119.38,44.704 ; 72.766,50.922 cw(c72.136,51.552) 72.136,50.661 ccw(c72.136,51.552) 72.766,50.922 ; 72.766,50.922 ccw(c73.396,50.292) 72.505,50.292 cw(c73.396,50.292) 72.766,50.922 ; 73.2,51.356 cw(c72.136,52.419) 72.136,50.915 ccw(c72.136,52.419) 73.2,51.356 ; 73.2,51.356 ccw(c74.263,50.292) 72.759,50.292 cw(c74.263,50.292) 73.2,51.356 ; 74.188,52.07 cw(c74.188,50.566) 75.251,51.629 ccw(c74.188,50.566) 74.188,52.07 ; 74.188,52.07 ccw(c74.188,53.574) 75.251,52.511 cw(c74.188,53.574) 74.188,52.07 ; 74.801,52.07 cw(c74.801,51.179) 75.431,51.809 ccw(c74.801,51.179) 74.801,52.07 ; 74.801,52.07 ccw(c74.801,52.961) 75.431,52.331 cw(c74.801,52.961) 74.801,52.07 ; 117.876,44.704 cw(c117.876,43.2) 118.939,44.263 ccw(c117.876,43.2) 117.876,44.704 ; 117.876,44.704 ccw(c117.876,46.208) 118.939,45.145 cw(c117.876,46.208) 117.876,44.704 ; 118.489,44.704 cw(c118.489,43.813) 119.119,44.443 ccw(c118.489,43.813) 118.489,44.704 ; 118.489,44.704 ccw(c118.489,45.595) 119.119,44.965 cw(c118.489,45.595) 118.489,44.704
  Bottom Layer w0.254: JP2.9@72.136,50.292 73.66,48.768 73.66,39.624 75.057,38.227 77.495,38.227 84.861,45.593 91.44,45.593 93.472,43.561 94.742,43.561 v1(95.91,44.729) ; 72.766,49.662 cw(c73.396,50.292) 72.505,50.292 ccw(c73.396,50.292) 72.766,49.662 ; 72.766,49.662 ccw(c72.136,49.032) 72.136,49.923 cw(c72.136,49.032) 72.766,49.662 ; 73.2,49.228 cw(c74.263,50.292) 72.759,50.292 ccw(c74.263,50.292) 73.2,49.228 ; 73.2,49.228 ccw(c72.136,48.165) 72.136,49.669 cw(c72.136,48.165) 73.2,49.228
AGND: C10.2 R9.2 R10.1 R13.2 R14.1 R22.1 U7.13 | length 106.6
  Top Layer w0.254: R9.2@107.53,121.92 R10.1@113.45,121.92 ; R14.1@134.962,112.776 138.303,112.776 ; v1(138.303,114.554) 138.303,112.776 ; U7.13@140.119,98.998 142.813,98.998 v1(142.875,99.06) ; R13.2@143.002,112.776 R13.2@142.914,112.776 138.303,112.776 ; 108.48,121.92 cw(c108.48,122.82) 107.844,122.184 ccw(c108.48,122.82) 108.48,121.92 ; 108.48,121.92 ccw(c108.48,121.02) 107.844,121.656 cw(c108.48,121.02) 108.48,121.92 ; 112.5,121.92 cw(c112.5,121.02) 113.136,121.656 ccw(c112.5,121.02) 112.5,121.92 ; 112.5,121.92 ccw(c112.5,122.82) 113.136,122.184 cw(c112.5,122.82) 112.5,121.92 ; 135.912,112.776 cw(c135.912,113.676) 135.276,113.04 ccw(c135.912,113.676) 135.912,112.776 ; 135.912,112.776 ccw(c135.912,111.876) 135.276,112.512 cw(c135.912,111.876) 135.912,112.776 ; 141.964,112.776 cw(c141.964,111.876) 142.6,112.512 ccw(c141.964,111.876) 141.964,112.776 ; 141.964,112.776 ccw(c141.964,113.676) 142.6,113.04 cw(c141.964,113.676) 141.964,112.776
  Top Layer w0.6: R10.1@113.45,121.92 113.45,120.23 119.126,114.554 R22.1@122.936,114.554 ; 121.97,114.554 cw(c121.97,113.588) 122.653,114.271 ccw(c121.97,113.588) 121.97,114.554 ; 121.97,114.554 ccw(c121.97,115.52) 122.653,114.837 cw(c121.97,115.52) 121.97,114.554
  Bottom Layer w0.254: R22.1@122.936,114.554 v1(138.303,114.554) 142.113,114.554 146.812,109.855 C10.2@146.812,99.02 142.875,99.02 142.835,99.02 v1(142.875,99.06) ; 123.706,114.554 cw(c123.706,115.324) 123.162,114.78 ccw(c123.706,115.324) 123.706,114.554 ; 123.706,114.554 ccw(c123.706,113.784) 123.162,114.328 cw(c123.706,113.784) 123.706,114.554 ; 124.319,114.554 cw(c124.319,115.937) 123.341,114.959 ccw(c124.319,115.937) 124.319,114.554 ; 124.319,114.554 ccw(c124.319,113.171) 123.341,114.149 cw(c124.319,113.171) 124.319,114.554 ; 145.489,99.02 cw(c145.489,97.697) 146.425,98.633 ccw(c145.489,97.697) 145.489,99.02 ; 145.489,99.02 ccw(c145.489,100.343) C10.2@146.425,99.408 ; 145.489,99.02 ccw(c145.489,100.343) C10.2@146.425,99.408 ; 146.102,99.02 cw(c146.102,98.31) 146.604,98.812 ccw(c146.102,98.31) 146.102,99.02 ; 146.102,99.02 ccw(c146.102,99.73) C10.2@146.604,99.228 ; 146.102,99.02 ccw(c146.102,99.73) C10.2@146.604,99.228 ; C10.2@146.425,99.408 ccw(c145.489,100.343) 146.812,100.343 ; C10.2@146.425,99.408 ccw(c145.489,100.343) 146.812,100.343 ; C10.2@146.604,99.228 ccw(c146.102,99.73) 146.812,99.73 ; C10.2@146.604,99.228 ccw(c146.102,99.73) 146.812,99.73 ; 146.812,99.73 ccw(c147.522,99.73) 147.02,99.228 cw(c147.522,99.73) 146.812,99.73 ; 146.812,100.343 ccw(c148.135,100.343) 147.199,99.408 cw(c148.135,100.343) 146.812,100.343
AINT0: U1.12
AP1.0: JP3.2 S1.4 S2.4 S3.4 U1.1 | length 122.1
  Top Layer w0.254: U1.1@90.932,31.75 92.329,31.75 ; S1.4@130.429,49.911 cw(c130.429,48.378) 131.513,49.462 cw(c132.597,50.546) S1.4@131.064,50.546 ; S1.4@130.429,50.165 cw(c130.429,49.245) 131.079,49.896 cw(c131.73,50.546) S1.4@130.81,50.546 ; S1.4@130.429,50.546 133.02,47.955 146.634,47.955 S2.4@149.225,50.546 ; S3.4@138.938,37.846 cw(c137.405,37.846) 138.489,36.762 cw(c139.573,35.678) S3.4@139.573,37.211 ; S3.4@139.192,37.846 cw(c138.272,37.846) 138.923,37.196 cw(c139.573,36.545) S3.4@139.573,37.465 ; S3.4@139.573,37.846 137.668,35.941 116.637,35.941 116.053,35.357 97.333,35.357 JP3.2@93.98,32.004 92.583,32.004 ; S2.4@148.59,50.546 cw(c147.057,50.546) 148.141,49.462 cw(c149.225,48.378) S2.4@149.225,49.911 ; S2.4@148.844,50.546 cw(c147.924,50.546) 148.575,49.896 cw(c149.225,49.245) S2.4@149.225,50.165 ; 91.759,31.75 cw(c91.759,32.493) 91.207,31.997 ccw(c91.759,32.493) 91.759,31.75 ; 91.759,31.75 ccw(c91.759,31.007) 91.207,31.503 cw(c91.759,31.007) 91.759,31.75 ; 92.329,31.75 cw(c92.329,33.005) 91.396,32.166 ccw(c92.329,33.005) 92.329,31.75 ; 92.329,31.75 ccw(c92.329,30.495) 91.396,31.334 cw(c92.329,30.495) 92.329,31.75 ; 92.329,31.75 92.583,32.004 ; 92.583,32.004 cw(c92.583,30.749) 93.516,31.588 ccw(c92.583,30.749) 92.583,32.004 ; 92.583,32.004 ccw(c92.583,33.259) 93.516,32.42 cw(c92.583,33.259) 92.583,32.004 ; 93.153,32.004 cw(c93.153,31.261) 93.705,31.757 ccw(c93.153,31.261) 93.153,32.004 ; 93.153,32.004 ccw(c93.153,32.747) 93.705,32.251 cw(c93.153,32.747) 93.153,32.004
  Bottom Layer w0.254: S1.4@130.429,49.911 cw(c130.429,48.378) 131.513,49.462 cw(c132.597,50.546) S1.4@131.064,50.546 ; S1.4@130.429,50.165 cw(c130.429,49.245) 131.079,49.896 cw(c131.73,50.546) S1.4@130.81,50.546 ; S1.4@130.429,50.546 132.461,48.514 132.461,43.434 138.049,37.846 ; S3.4@139.122,37.399 ccw(c138.049,36.335) 138.049,37.846 ; S3.4@139.122,38.293 cw(c138.049,39.357) 138.049,37.846 ; S3.4@139.302,37.578 ccw(c138.659,36.939) 138.659,37.846 ccw(c138.659,38.753) S3.4@139.302,38.114 ; S3.4@139.573,37.846 138.049,37.846
AP1.1: JP3.3 S6.4 U1.2 | length 120.2
  Top Layer w0.254: U1.2@90.932,34.29 92.329,34.29 ; v1(92.253,30.734) 111.379,30.734 113.919,33.274 139.675,33.274 140.716,34.315 140.716,46.482 140.462,46.736 131.953,46.736 129.286,49.403 129.286,51.511 130.048,52.273 137.846,52.273 S6.4@139.573,50.546 ; JP3.3@93.98,34.544 92.583,34.544 ; S6.4@138.938,50.546 ccw(c137.405,50.546) 138.489,51.63 ccw(c139.573,52.714) S6.4@139.573,51.181 ; S6.4@139.192,50.546 ccw(c138.272,50.546) 138.923,51.196 ccw(c139.573,51.847) S6.4@139.573,50.927 ; 91.759,34.29 cw(c91.759,35.033) 91.207,34.537 ccw(c91.759,35.033) 91.759,34.29 ; 91.759,34.29 ccw(c91.759,33.547) 91.207,34.043 cw(c91.759,33.547) 91.759,34.29 ; 92.329,34.29 cw(c92.329,35.545) 91.396,34.706 ccw(c92.329,35.545) 92.329,34.29 ; 92.329,34.29 ccw(c92.329,33.035) 91.396,33.874 cw(c92.329,33.035) 92.329,34.29 ; 92.329,34.29 92.583,34.544 ; 92.583,34.544 cw(c92.583,33.289) 93.516,34.128 ccw(c92.583,33.289) 92.583,34.544 ; 92.583,34.544 ccw(c92.583,35.799) 93.516,34.96 cw(c92.583,35.799) 92.583,34.544 ; 93.153,34.544 cw(c93.153,33.801) 93.705,34.297 ccw(c93.153,33.801) 93.153,34.544 ; 93.153,34.544 ccw(c93.153,35.287) 93.705,34.791 cw(c93.153,35.287) 93.153,34.544
  Bottom Layer w0.254: U1.2@90.932,34.29 92.253,32.969 v1(92.253,30.734) ; 91.562,33.66 cw(c92.192,34.29) 91.301,34.29 ccw(c92.192,34.29) 91.562,33.66 ; 91.562,33.66 ccw(c90.932,33.03) 90.932,33.921 cw(c90.932,33.03) 91.562,33.66 ; 91.996,33.226 cw(c93.059,34.29) 91.555,34.29 ccw(c93.059,34.29) 91.996,33.226 ; 91.996,33.226 ccw(c90.932,32.163) 90.932,33.667 cw(c90.932,32.163) 91.996,33.226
